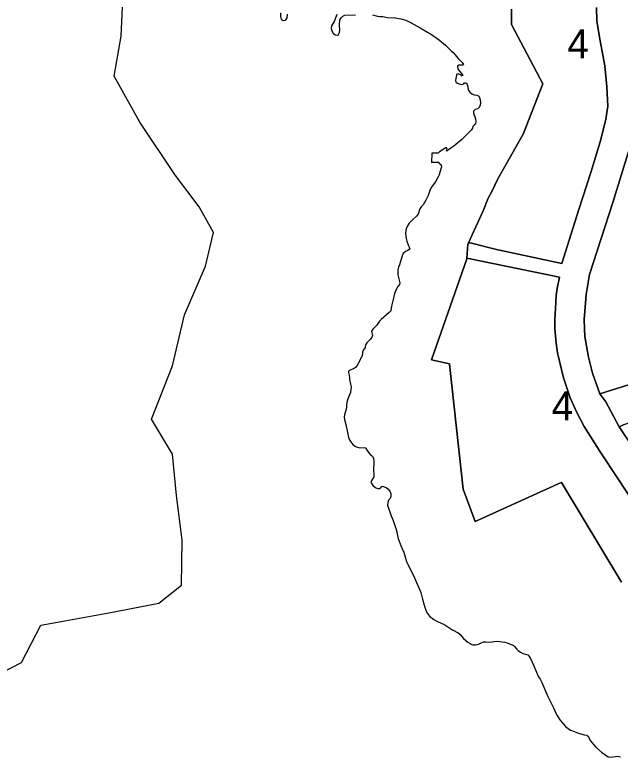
# Model space of a CAD drawing. Extents: x 598968 to 613553, y 4409678 to 4430833.
# Drawn here: x 599800.7 to 600050.4, y 4411604.6 to 4411910.9 of the extents above; entities that cross this region are included whole.
import ezdxf

# ---------------------------------------------------------------- set-up
doc = ezdxf.new("R2010")
doc.units = 0
for name, color, linetype in [('1', 7, 'Continuous'), ('Sòl Rústic Protegit - Alt Nivell de Protecció', 7, 'Continuous'), ('ZONA 4. CASES UNIFAMILIRAS AÏLLADES EN PARCEL.LES', 7, 'Continuous')]:
    doc.layers.add(name, color=color, linetype=linetype)

msp = doc.modelspace()

# ---------------------------------------------------------------- linework, layer by layer
at = {"layer": '1'}
for points in [[(599910.3154, 4411911.6452), (599910.2354, 4411910.6452), (599910.2554, 4411910.1652), (599910.5654, 4411909.0953), (599911.4154, 4411908.4954), (599911.4534, 4411908.5044), (599912.3854, 4411908.7254), (599912.4754, 4411908.7954), (599913.0154, 4411909.6454), (599913.1854, 4411911.1854)], [(600050.9302, 4411676.811), (600026.1306, 4411717.9904), (600026.101, 4411717.977), (599990.5511, 4411701.9099), (599990.5182, 4411701.8949), (599985.5911, 4411715.21), (599979.9688, 4411766.7813), (599979.9614, 4411766.8495), (599972.5915, 4411768.5694), (599987.0715, 4411810.2592), (599987.0859, 4411810.4496), (599987.5215, 4411816.2092), (599987.8066, 4411816.8313), (599993.8728, 4411830.0673), (599996.0023, 4411835.2943), (599997.4968, 4411837.9743), (599999.8914, 4411843.1991), (600010.4335, 4411861.5858), (600018.5213, 4411882.3591), (600005.5766, 4411906.8887), (600005.5916, 4411913.2687)], [(600040.5684, 4411913.9009), (600040.8318, 4411908.2859), (600042.1791, 4411900.0742), (600044.132, 4411889.8738), (600044.8268, 4411881.1453), (600045.24, 4411873.2243), (600044.8415, 4411870.5525), (600044.4203, 4411867.7285), (600042.1503, 4411858.4137), (600038.2697, 4411845.8141), (600033.2508, 4411830.1627), (600026.2802, 4411808.3528), (599999.3911, 4411814.0766), (599988.4499, 4411816.7558), (599987.8066, 4411816.8313), (599987.5215, 4411816.2092), (599987.0859, 4411810.4496), (600025.3251, 4411802.7024), (600024.4257, 4411797.9854), (600023.9699, 4411795.0935), (600023.6613, 4411789.6164), (600023.3868, 4411785.3559), (600023.4781, 4411781.3866), (600023.936, 4411775.3899), (600024.5754, 4411771.375), (600026.9968, 4411761.0861), (600029.8191, 4411752.8375), (600032.5547, 4411746.7636), (600035.523, 4411741.0939), (600042.4707, 4411730.1817), (600049.1762, 4411720.0514), (600060.6089, 4411702.7136)], [(599933.4749, 4411910.9958), (599932.4049, 4411908.1358), (599932.3849, 4411908.1058), (599931.3449, 4411906.2658), (599931.2349, 4411905.2258), (599931.4549, 4411904.2558), (599932.0148, 4411903.2858), (599932.8248, 4411902.6659), (599932.9146, 4411902.6458), (599933.7648, 4411902.456), (599934.1648, 4411902.746), (599934.6448, 4411903.546), (599934.7448, 4411904.5059), (599934.6048, 4411906.6858), (599934.6248, 4411907.6758), (599934.6848, 4411908.0158), (599934.8048, 4411908.7858), (599935.2548, 4411909.6958), (599935.9848, 4411910.3758), (599936.8348, 4411910.6858), (599941.1547, 4411910.916)], [(599948.1846, 4411910.8962), (599950.2645, 4411910.3662), (599951.2544, 4411910.2162), (599952.4544, 4411910.1262), (599954.4344, 4411909.8362), (599957.5043, 4411909.6664), (599957.7043, 4411909.6564), (599959.8642, 4411909.2064), (599961.9442, 4411908.6064), (599963.9342, 4411907.6966), (599964.119, 4411907.5935), (599967.824, 4411905.5266), (599972.5439, 4411902.6868), (599975.9038, 4411900.3569), (599978.3437, 4411898.377), (599980.6536, 4411896.007), (599981.4436, 4411895.2971), (599983.7636, 4411892.7572), (599985.2735, 4411891.2672), (599985.7835, 4411890.3872), (599985.4735, 4411890.0772), (599984.0835, 4411890.0572), (599983.7935, 4411890.0572), (599983.2836, 4411889.7072), (599983.2436, 4411889.2372), (599983.5635, 4411888.3772), (599984.1535, 4411887.5672), (599984.9535, 4411886.6773), (599985.4334, 4411885.7974), (599985.0441, 4411885.7431), (599985.0034, 4411885.7374), (599984.5355, 4411886.0649), (599984.5035, 4411886.0873), (599983.5935, 4411886.5572), (599983.0435, 4411886.4272), (599982.8535, 4411885.9772), (599982.4035, 4411883.9772), (599982.5735, 4411883.0473), (599983.0435, 4411882.7774), (599983.0755, 4411882.7658), (599983.9834, 4411882.4374), (599985.0534, 4411882.1774), (599985.8434, 4411882.3374), (599986.1234, 4411882.7774), (599986.6834, 4411882.8574), (599986.8268, 4411882.728), (599987.0934, 4411882.4874), (599987.3934, 4411881.7574), (599987.4834, 4411880.7574), (599987.7734, 4411879.7574), (599988.3834, 4411878.9275), (599989.1933, 4411878.3176), (599989.3233, 4411878.2576), (599989.3586, 4411878.2389), (599990.1533, 4411877.8176), (599991.2132, 4411877.7176), (599992.1132, 4411877.2976), (599992.1247, 4411877.2754), (599992.3832, 4411876.7776), (599992.6632, 4411875.8176), (599992.7432, 4411874.5976), (599992.6232, 4411873.6076), (599992.2332, 4411872.5976), (599991.6332, 4411872.0976), (599990.6232, 4411871.7876), (599989.8932, 4411871.1777), (599989.8332, 4411870.6177), (599990.0432, 4411869.6477), (599990.4632, 4411868.9278), (599990.7632, 4411867.9778), (599990.8832, 4411866.8078), (599990.7532, 4411865.8178), (599990.2932, 4411865.4978), (599989.5732, 4411864.8078), (599989.4232, 4411864.1578), (599988.9032, 4411863.2978), (599987.4132, 4411861.7378), (599985.0533, 4411859.4878), (599981.7634, 4411856.7477), (599980.5634, 4411855.8477), (599979.2134, 4411854.8377), (599979.0364, 4411854.7509), (599978.7034, 4411854.5877), (599979.0734, 4411855.4977), (599978.9243, 4411855.8332), (599978.8734, 4411855.9477), (599978.4834, 4411855.9576), (599977.7634, 4411855.6076), (599975.8234, 4411854.3676), (599975.3634, 4411853.7676), (599972.7436, 4411853.7676), (599972.6235, 4411850.0176), (599972.8458, 4411850.0236), (599975.5634, 4411850.0977), (599975.5892, 4411849.9737), (599975.6134, 4411849.8577), (599976.4834, 4411848.9277), (599976.5034, 4411848.8277), (599976.6234, 4411848.2177), (599976.4434, 4411847.3578), (599976.0934, 4411846.4178), (599975.6634, 4411844.9178), (599975.2934, 4411843.9878), (599974.1734, 4411841.9878), (599972.8534, 4411840.1578), (599972.3134, 4411839.3178), (599971.8534, 4411838.4278), (599971.1234, 4411836.3878), (599970.1934, 4411834.3778), (599969.7134, 4411833.4378), (599969.0734, 4411832.4978), (599968.3435, 4411831.6378), (599967.8035, 4411830.7978), (599967.0435, 4411828.6978), (599966.3835, 4411827.8478), (599964.8735, 4411826.4378), (599963.3236, 4411824.8678), (599962.7136, 4411823.8678), (599962.2636, 4411822.8078), (599961.9636, 4411821.8578), (599961.8836, 4411820.6678), (599962.1236, 4411818.6378), (599962.3435, 4411817.5478), (599963.0535, 4411815.5479), (599963.5734, 4411814.488), (599963.3934, 4411814.008), (599962.8235, 4411813.5879), (599961.8535, 4411813.2779), (599960.9035, 4411812.3879), (599960.4635, 4411811.4879), (599959.3035, 4411807.708), (599958.9235, 4411806.728), (599958.7235, 4411805.658), (599958.6535, 4411804.658), (599958.7035, 4411803.608), (599959.5334, 4411800.278), (599959.3034, 4411799.648), (599958.6935, 4411798.858), (599958.1235, 4411797.888), (599957.3435, 4411795.9181), (599956.5535, 4411792.8381), (599956.0835, 4411790.6781), (599955.9635, 4411789.6881), (599955.7234, 4411788.7182), (599955.0935, 4411788.0682), (599951.8036, 4411785.2381), (599951.1036, 4411784.5181), (599949.8936, 4411782.7581), (599949.1436, 4411781.9781), (599948.3236, 4411781.2381), (599947.8236, 4411780.3681), (599947.9036, 4411779.6181), (599948.1636, 4411778.6481), (599947.9236, 4411777.9581), (599947.3536, 4411777.0481), (599945.8736, 4411775.5881), (599945.3636, 4411774.7281), (599945.1336, 4411773.6681), (599944.5436, 4411772.6981), (599944.1136, 4411771.7481), (599944.1136, 4411770.8382), (599943.7836, 4411769.8982), (599943.2336, 4411768.9482), (599942.4236, 4411767.1082), (599941.8536, 4411766.1982), (599941.1436, 4411765.4182), (599940.3436, 4411764.8182), (599940.0336, 4411764.6882), (599939.2737, 4411764.3781), (599938.3837, 4411763.8581), (599938.3337, 4411763.3081), (599938.5637, 4411762.2382), (599938.6937, 4411761.1582), (599938.7736, 4411760.4582), (599939.2136, 4411758.4582), (599939.3736, 4411757.3682), (599939.1136, 4411755.1382), (599938.2936, 4411753.0783), (599937.6736, 4411751.0683), (599937.3236, 4411747.9383), (599937.2636, 4411747.7383), (599936.6836, 4411745.8984), (599936.5536, 4411744.9084), (599936.6936, 4411743.8884), (599937.2836, 4411741.8084), (599937.8536, 4411738.5385), (599938.3335, 4411736.4885), (599938.9135, 4411735.2886), (599939.5134, 4411734.3486), (599940.2134, 4411733.5186), (599941.0134, 4411732.9186), (599941.1496, 4411732.861), (599942.0534, 4411732.4786), (599943.0234, 4411732.2487), (599943.0434, 4411732.2487), (599945.1833, 4411732.3387), (599945.303, 4411732.2153), (599945.5033, 4411732.0088), (599945.9933, 4411731.1388), (599946.6432, 4411730.1988), (599947.4032, 4411729.3788), (599948.2032, 4411728.7588), (599948.6232, 4411727.8989), (599948.7732, 4411726.9089), (599948.7832, 4411725.8889), (599948.6632, 4411723.599), (599948.7032, 4411723.089), (599948.8332, 4411721.319), (599948.8032, 4411720.319), (599948.4232, 4411719.599), (599947.7432, 4411718.819), (599947.5932, 4411717.999), (599947.8832, 4411717.329), (599948.5331, 4411716.569), (599949.4531, 4411715.8691), (599949.6255, 4411715.7848), (599950.373, 4411715.4191), (599950.483, 4411715.4291), (599951.383, 4411715.4391), (599951.543, 4411715.8391), (599952.263, 4411716.3791), (599952.763, 4411716.2992), (599953.783, 4411715.8992), (599953.8994, 4411715.8198), (599954.603, 4411715.3392), (599955.373, 4411714.3992), (599955.723, 4411713.3892), (599955.7629, 4411712.5193), (599955.7729, 4411712.3193), (599955.4829, 4411711.3593), (599954.863, 4411710.6293), (599954.513, 4411709.6893), (599954.4629, 4411708.6593), (599955.9728, 4411704.1794), (599956.6828, 4411702.3094), (599958.1328, 4411698.1395), (599958.4828, 4411696.0696), (599958.8427, 4411694.7196), (599959.1827, 4411693.7396), (599959.5927, 4411692.6596), (599960.8826, 4411689.6597), (599961.0826, 4411689.1997), (599962.1626, 4411685.6998), (599962.5726, 4411684.6898), (599962.6326, 4411684.5298), (599965.5724, 4411678.64), (599967.7624, 4411673.5101), (599968.1024, 4411672.5601), (599968.8723, 4411669.7802), (599969.4923, 4411667.2802), (599969.9122, 4411666.0403), (599970.3622, 4411664.9203), (599970.9022, 4411663.8503), (599971.7822, 4411662.8404), (599973.5122, 4411661.4704), (599974.9821, 4411660.6205), (599975.3321, 4411660.4205), (599975.3618, 4411660.4086), (599977.522, 4411659.5406), (599977.6554, 4411659.4547), (599981.392, 4411657.0506), (599981.5243, 4411656.9863), (599983.3019, 4411656.1207), (599983.3615, 4411656.0781), (599984.2818, 4411655.4208), (599985.8118, 4411653.6408), (599987.5218, 4411652.1409), (599988.4618, 4411651.5009), (599988.5757, 4411651.4522), (599989.6317, 4411651.001), (599990.8616, 4411650.921), (599992.0116, 4411651.311), (599993.1016, 4411651.771), (599994.2016, 4411652.201), (599995.0416, 4411652.201), (599996.3316, 4411652.1411), (599999.6915, 4411652.4912), (600002.8814, 4411652.0812), (600003.8414, 4411651.7812), (600006.1413, 4411650.8913), (600006.2038, 4411650.8314), (600006.8413, 4411650.2214), (600007.5812, 4411649.3514), (600008.3812, 4411648.6014), (600009.2812, 4411647.9714), (600010.2212, 4411647.4014), (600010.2574, 4411647.3919), (600012.3512, 4411646.8415), (600012.4203, 4411646.7604), (600012.8712, 4411646.2315), (600013.3911, 4411645.3016), (600014.751, 4411642.3116), (600016.141, 4411639.0017), (600016.761, 4411637.8118), (600017.4209, 4411636.7517), (600018.0109, 4411635.3717), (600020.5108, 4411629.6019), (600022.8507, 4411625.052), (600024.2806, 4411622.0121), (600024.7806, 4411621.1021), (600025.5306, 4411619.9921), (600027.8506, 4411617.3122), (600028.8705, 4411616.4922), (600029.9504, 4411615.8223), (600030.0221, 4411615.7931), (600032.0604, 4411614.9623), (600033.2204, 4411614.5923), (600035.5904, 4411613.8524), (600036.5703, 4411613.7525), (600036.7352, 4411613.6369), (600037.3403, 4411613.2125), (600037.6502, 4411612.4025), (600038.1802, 4411611.4225), (600039.4602, 4411609.6826), (600040.3402, 4411608.7526), (600042.7301, 4411606.6827), (600045.37, 4411604.8328), (600045.4346, 4411604.8204), (600046.36, 4411604.6428), (600049.48, 4411604.9929), (600050.5, 4411604.7129)], [(600061.5012, 4411723.6532), (600049.9304, 4411740.9694), (600044.4883, 4411751.225), (600042.0429, 4411754.5468), (600038.9306, 4411763.0502), (600037.315, 4411769.6927), (600035.8327, 4411778.1242), (600035.672, 4411781.2965), (600035.4728, 4411785.2386), (600036.4071, 4411795.5152), (600037.7662, 4411803.8102), (600047.3083, 4411833.433), (600055.9112, 4411861.0664)]]:
    msp.add_lwpolyline(points, dxfattribs=at)
msp.add_lwpolyline([(600049.9304, 4411740.9694), (600052.0836, 4411741.8423), (600062.8768, 4411745.6779), (600075.5368, 4411748.9747), (600072.5046, 4411757.8138), (600070.8636, 4411763.3722), (600053.8601, 4411758.1654), (600042.0429, 4411754.5468), (600044.4883, 4411751.225)], close=True, dxfattribs=at)
at = {"layer": 'Sòl Rústic Protegit - Alt Nivell de Protecció'}
msp.add_lwpolyline([(599795.5255, 4411639.6282), (599803.4631, 4411643.6284), (599811.4631, 4411659.1284), (599819.8381, 4411660.6284), (599839.4627, 4411664.1286), (599860.0249, 4411668.1288), (599869.4623, 4411675.6288), (599869.7749, 4411694.1288), (599867.4001, 4411712.6286), (599865.7127, 4411729.6284), (599857.0877, 4411744.1282), (599865.7127, 4411766.1282), (599870.6503, 4411787.128), (599879.4003, 4411807.128), (599882.6503, 4411821.128), (599876.7131, 4411831.6278), (599866.9631, 4411844.6276), (599852.2757, 4411866.6272), (599841.7135, 4411885.627), (599844.5261, 4411902.127), (599845.5261, 4411923.1268)], dxfattribs=at)
at = {"layer": 'ZONA 4. CASES UNIFAMILIRAS AÏLLADES EN PARCEL.LES'}
for points in [[(600005.5916, 4411913.2687), (600005.5766, 4411906.8887), (600018.5213, 4411882.3591), (600010.4335, 4411861.5858), (599999.8914, 4411843.1991), (599997.4968, 4411837.9743), (599996.0023, 4411835.2943), (599993.8728, 4411830.0673), (599987.8066, 4411816.8313), (599988.4499, 4411816.7558), (599999.3911, 4411814.0766), (600026.2802, 4411808.3528), (600033.2508, 4411830.1627), (600038.2697, 4411845.8141), (600042.1503, 4411858.4137), (600044.4203, 4411867.7285), (600044.8415, 4411870.5525), (600045.24, 4411873.2243), (600044.8268, 4411881.1453), (600044.132, 4411889.8738), (600042.1791, 4411900.0742), (600040.8318, 4411908.2859), (600040.5684, 4411913.9009)], [(600055.9112, 4411861.0664), (600047.3083, 4411833.433), (600037.7662, 4411803.8102), (600036.4071, 4411795.5152), (600035.4728, 4411785.2386), (600035.672, 4411781.2965), (600035.8327, 4411778.1242), (600037.315, 4411769.6927), (600038.9306, 4411763.0502), (600042.0429, 4411754.5468), (600053.8601, 4411758.1654)], [(600060.6089, 4411702.7136), (600049.1762, 4411720.0514), (600042.4707, 4411730.1817), (600035.523, 4411741.0939), (600032.5547, 4411746.7636), (600029.8191, 4411752.8375), (600026.9968, 4411761.0861), (600024.5754, 4411771.375), (600023.936, 4411775.3899), (600023.4781, 4411781.3866), (600023.3868, 4411785.3559), (600023.6613, 4411789.6164), (600023.9699, 4411795.0935), (600024.4257, 4411797.9854), (600025.3251, 4411802.7024), (599987.0859, 4411810.4496), (599987.0715, 4411810.2592), (599972.5915, 4411768.5694), (599979.9614, 4411766.8495), (599979.9688, 4411766.7813), (599985.5911, 4411715.21), (599990.5182, 4411701.8949), (599990.5511, 4411701.9099), (600026.101, 4411717.977), (600026.1306, 4411717.9904), (600050.9302, 4411676.811)], [(600052.0836, 4411741.8423), (600049.9304, 4411740.9694), (600061.5012, 4411723.6532)]]:
    msp.add_lwpolyline(points, dxfattribs=at)

# ---------------------------------------------------------------- texts
for p in [(600028.5748, 4411892.9427), (600022.1173, 4411743.5329)]:
    msp.add_text('4', height=12, dxfattribs=at).set_placement(p)

doc.saveas('drawing.dxf')
